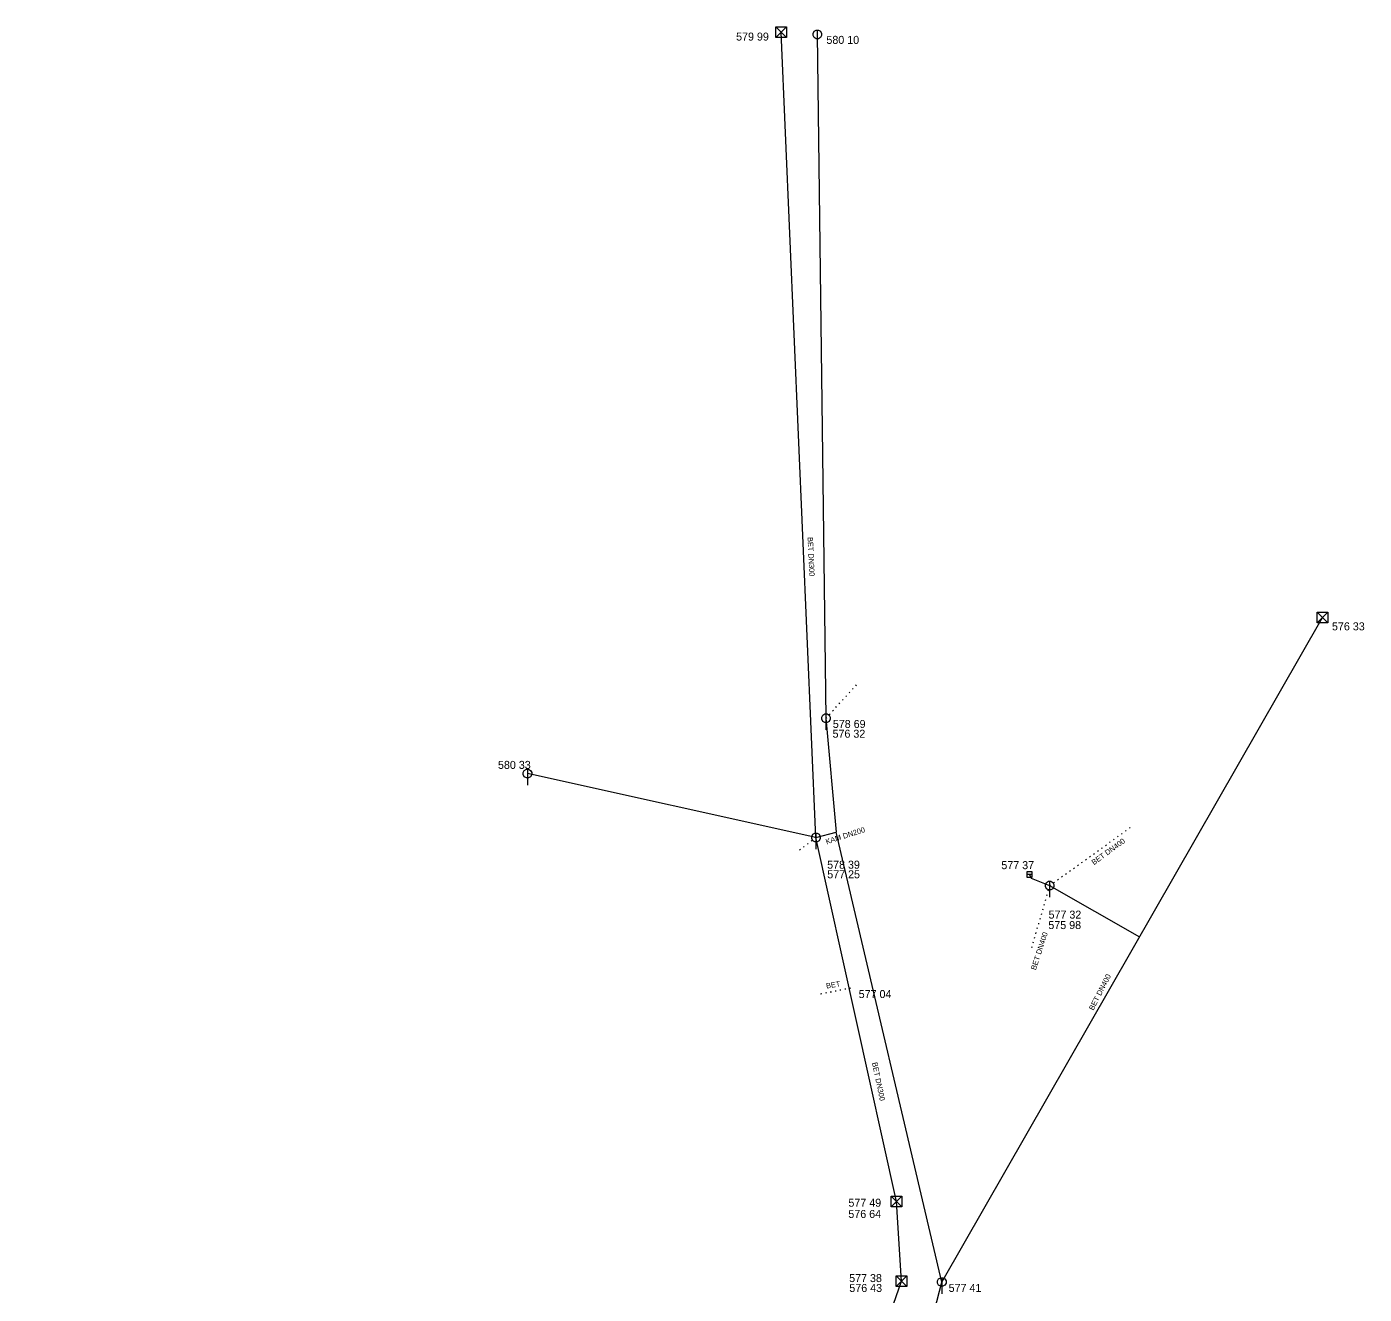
# Model space of a CAD drawing. Extents: x -710806 to -710046, y -1116920 to -1116046.
# Drawn here: x -710171.4 to -710046.1, y -1116165.1 to -1116046.3 of the extents above; entities that cross this region are included whole.
import ezdxf
from ezdxf.enums import TextEntityAlignment as Align

# ---------------------------------------------------------------- set-up
doc = ezdxf.new("R2010")
doc.units = 0
doc.header["$LTSCALE"] = 0.3
doc.linetypes.add('DOTTED', pattern=[1.5, 0.3, -1.2])
for name, color, linetype, lineweight in [('40', 7, 'Continuous', 13), ('41', 7, 'Continuous', 13), ('45', 7, 'DOTTED', 13)]:
    doc.layers.add(name, color=color, linetype=linetype, lineweight=lineweight)
doc.layers.add('43', color=7, linetype='Continuous')
doc.layers.add('44', color=7, linetype='Continuous')

msp = doc.modelspace()

# ---------------------------------------------------------------- linework, layer by layer
at = {"layer": '40'}
for p, q in [((-710097.496, -1116122.299), (-710100.752, -1116046.806)), ((-710097.368, -1116047.024), (-710096.558, -1116111.116)), ((-710085.71, -1116163.96), (-710050.039, -1116101.685)), ((-710096.558, -1116111.116), (-710095.598, -1116121.8)), ((-710097.496, -1116122.299), (-710095.598, -1116121.8)), ((-710085.71, -1116163.96), (-710095.598, -1116121.8)), ((-710075.599, -1116126.8), (-710067.185, -1116131.619))]:
    msp.add_line(p, q, dxfattribs=at)
at = {"layer": '40', "linetype": 'DOTTED'}
for q in [(-710067.932, -1116121.294), (-710077.313, -1116132.672)]:
    msp.add_line((-710075.599, -1116126.8), q, dxfattribs=at)
at = {"layer": '40'}
for points in [[(-710097.606, -1116199.871), (-710101.52, -1116198.471), (-710089.481, -1116163.872), (-710089.946, -1116156.41), (-710097.496, -1116122.299), (-710124.534, -1116116.307)], [(-710171.446, -1116284.268), (-710145.874, -1116273.486), (-710131.257, -1116265.793), (-710127.793, -1116263.212), (-710120.495, -1116254.452), (-710110.653, -1116236.079), (-710102.507, -1116213.21), (-710087.53, -1116171.086), (-710085.71, -1116163.96)]]:
    msp.add_lwpolyline(points, dxfattribs=at)
at = {"layer": '41'}
for p, q in [((-710101.252, -1116046.306), (-710100.252, -1116047.306)), ((-710100.252, -1116046.306), (-710101.252, -1116047.306)), ((-710097.368, -1116046.624), (-710097.368, -1116048.124)), ((-710050.539, -1116101.185), (-710049.539, -1116102.185)), ((-710049.539, -1116101.185), (-710050.539, -1116102.185)), ((-710096.558, -1116110.716), (-710096.558, -1116112.216)), ((-710124.534, -1116115.907), (-710124.534, -1116117.407)), ((-710097.496, -1116121.899), (-710097.496, -1116123.399)), ((-710077.246, -1116125.506), (-710077.746, -1116125.506)), ((-710077.746, -1116125.506), (-710077.746, -1116126.006)), ((-710077.246, -1116125.756), (-710077.746, -1116125.756)), ((-710077.246, -1116126.006), (-710077.246, -1116125.506)), ((-710077.746, -1116126.006), (-710077.246, -1116126.006)), ((-710075.599, -1116126.4), (-710075.599, -1116127.9)), ((-710090.446, -1116155.91), (-710089.446, -1116156.91)), ((-710089.446, -1116155.91), (-710090.446, -1116156.91)), ((-710089.981, -1116163.372), (-710088.981, -1116164.372)), ((-710088.981, -1116163.372), (-710089.981, -1116164.372)), ((-710085.71, -1116163.56), (-710085.71, -1116165.06))]:
    msp.add_line(p, q, dxfattribs=at)
for points in [[(-710101.252, -1116046.306), (-710100.252, -1116046.306), (-710100.252, -1116047.306), (-710101.252, -1116047.306)], [(-710097.768, -1116047.124), (-710097.768, -1116046.924), (-710097.668, -1116046.724), (-710097.468, -1116046.624), (-710097.268, -1116046.624), (-710097.068, -1116046.724), (-710096.968, -1116046.924), (-710096.968, -1116047.124), (-710097.068, -1116047.324), (-710097.268, -1116047.424), (-710097.468, -1116047.424), (-710097.668, -1116047.324)], [(-710050.539, -1116101.185), (-710049.539, -1116101.185), (-710049.539, -1116102.185), (-710050.539, -1116102.185)], [(-710096.958, -1116111.216), (-710096.958, -1116111.016), (-710096.858, -1116110.816), (-710096.658, -1116110.716), (-710096.458, -1116110.716), (-710096.258, -1116110.816), (-710096.158, -1116111.016), (-710096.158, -1116111.216), (-710096.258, -1116111.416), (-710096.458, -1116111.516), (-710096.658, -1116111.516), (-710096.858, -1116111.416)], [(-710124.934, -1116116.407), (-710124.934, -1116116.207), (-710124.834, -1116116.007), (-710124.634, -1116115.907), (-710124.434, -1116115.907), (-710124.234, -1116116.007), (-710124.134, -1116116.207), (-710124.134, -1116116.407), (-710124.234, -1116116.607), (-710124.434, -1116116.707), (-710124.634, -1116116.707), (-710124.834, -1116116.607)], [(-710097.896, -1116122.399), (-710097.896, -1116122.199), (-710097.796, -1116121.999), (-710097.596, -1116121.899), (-710097.396, -1116121.899), (-710097.196, -1116121.999), (-710097.096, -1116122.199), (-710097.096, -1116122.399), (-710097.196, -1116122.599), (-710097.396, -1116122.699), (-710097.596, -1116122.699), (-710097.796, -1116122.599)], [(-710075.999, -1116126.9), (-710075.999, -1116126.7), (-710075.899, -1116126.5), (-710075.699, -1116126.4), (-710075.499, -1116126.4), (-710075.299, -1116126.5), (-710075.199, -1116126.7), (-710075.199, -1116126.9), (-710075.299, -1116127.1), (-710075.499, -1116127.2), (-710075.699, -1116127.2), (-710075.899, -1116127.1)], [(-710090.446, -1116155.91), (-710089.446, -1116155.91), (-710089.446, -1116156.91), (-710090.446, -1116156.91)], [(-710089.981, -1116163.372), (-710088.981, -1116163.372), (-710088.981, -1116164.372), (-710089.981, -1116164.372)], [(-710086.11, -1116164.06), (-710086.11, -1116163.86), (-710086.01, -1116163.66), (-710085.81, -1116163.56), (-710085.61, -1116163.56), (-710085.41, -1116163.66), (-710085.31, -1116163.86), (-710085.31, -1116164.06), (-710085.41, -1116164.26), (-710085.61, -1116164.36), (-710085.81, -1116164.36), (-710086.01, -1116164.26)]]:
    msp.add_lwpolyline(points, close=True, dxfattribs=at)
at = {"layer": '45'}
for p, q in [((-710096.558, -1116111.116), (-710093.515, -1116107.805)), ((-710097.496, -1116122.299), (-710099.113, -1116123.546)), ((-710094.251, -1116136.418), (-710097.293, -1116137.028))]:
    msp.add_line(p, q, dxfattribs=at)
at = {"layer": '45', "linetype": 'Continuous'}
msp.add_lwpolyline([(-710077.496, -1116125.756), (-710077.321, -1116126.123), (-710075.599, -1116126.8)], dxfattribs=at)

# ---------------------------------------------------------------- texts
at = {"layer": '43'}
for s, p in [('579 99 ', (-710103.3052, -1116047.604)), ('580 10 ', (-710094.8442, -1116047.912)), ('576 33 ', (-710047.4712, -1116102.881)), ('578 69 ', (-710094.2422, -1116112.03)), ('580 33 ', (-710125.6172, -1116115.867)), ('578 39 ', (-710094.7752, -1116125.222)), ('577 37 ', (-710078.4522, -1116125.264)), ('577 32 ', (-710074.0292, -1116129.901)), ('577 04 ', (-710091.8182, -1116137.346)), ('577 49 ', (-710092.7812, -1116156.904)), ('577 38 ', (-710092.7122, -1116163.967)), ('577 41 ', (-710083.3902, -1116164.888))]:
    msp.add_text(s, height=0.75, dxfattribs=at).set_placement(p, align=Align.CENTER)
for s, p in [('576 32', (-710095.943, -1116112.944)), ('577 25', (-710096.437, -1116126.12)), ('575 98', (-710075.721, -1116130.879)), ('576 64', (-710094.461, -1116157.957)), ('576 43', (-710094.369, -1116164.893))]:
    msp.add_text(s, height=0.75, dxfattribs=at).set_placement(p)
at = {"layer": '44'}
for s, rotation, p in [('BET DN300', 272.7, (-710098.285, -1116094.147)), ('KAM DN200', 18, (-710096.497, -1116122.951)), ('BET DN400', 36, (-710071.447, -1116124.902)), ('BET DN400', 72, (-710076.898, -1116134.767)), ('BET', 9, (-710096.509, -1116136.457)), ('BET DN400', 63, (-710071.503, -1116138.543)), ('BET DN300', 281.7, (-710092.245, -1116143.413))]:
    msp.add_text(s, height=0.5, rotation=rotation, dxfattribs=at).set_placement(p)

doc.saveas('drawing.dxf')
